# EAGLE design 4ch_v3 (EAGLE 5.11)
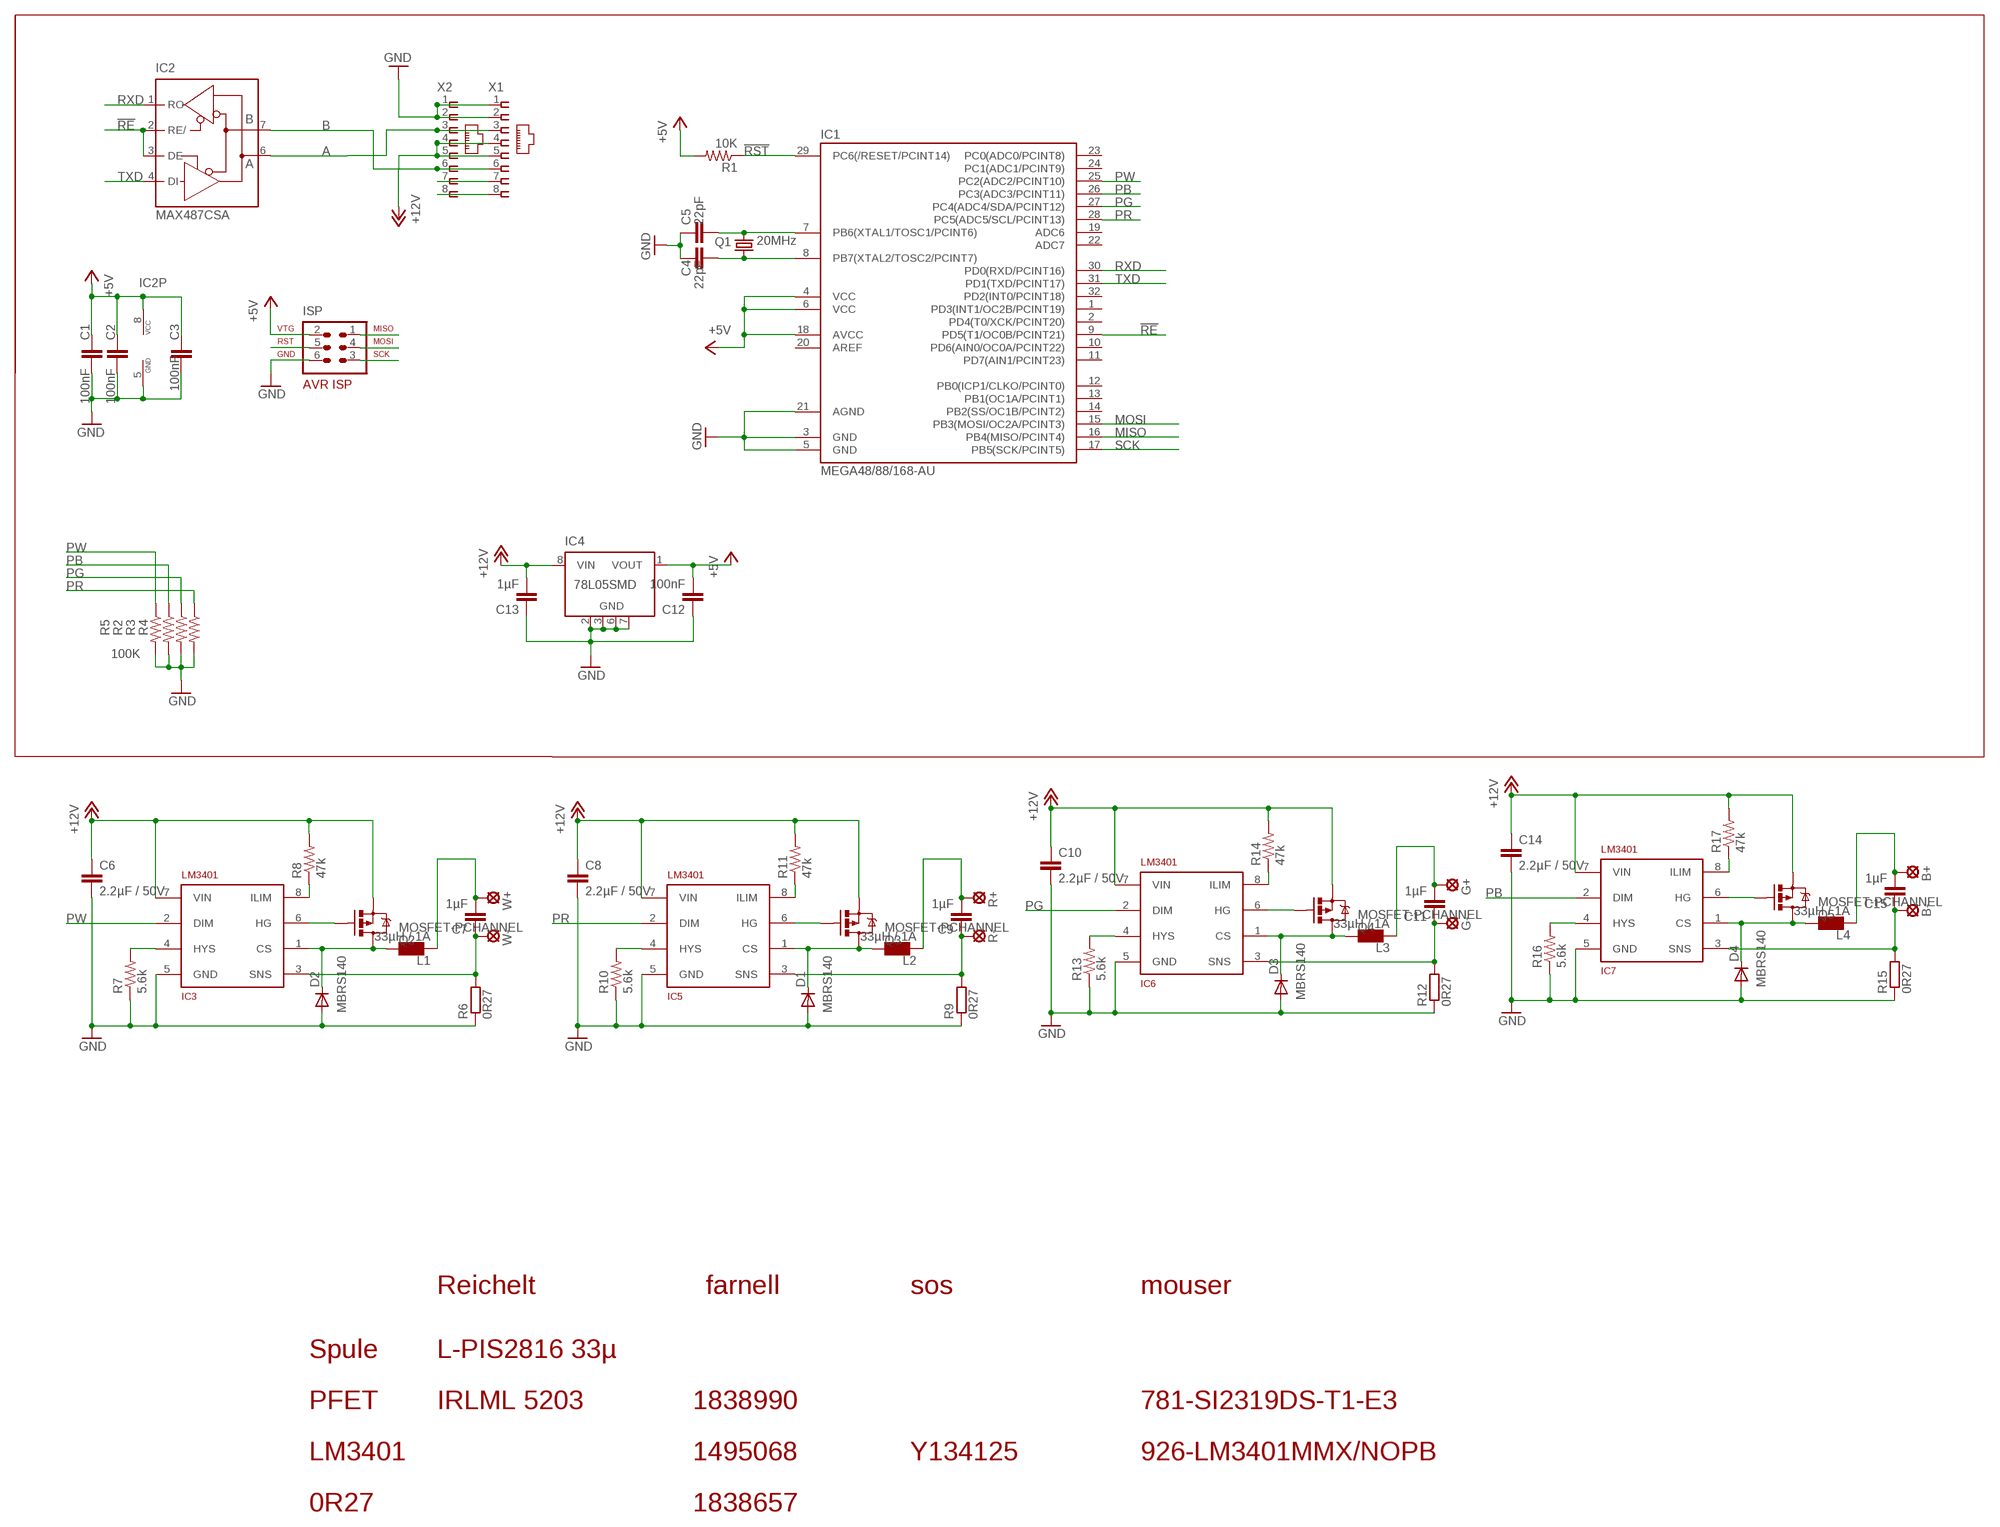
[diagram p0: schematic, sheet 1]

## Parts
B+  SE14  [SE14]
B-  SE14  [SE14]
C1  100nF  CAP0402-CAP  [0402-CAP]
C2  100nF  CAP0402-CAP  [0402-CAP]
C3  100nF  CAP0402-CAP  [0402-CAP]
C4  22pF  CAP0402-CAP  [0402-CAP]
C5  22pF  CAP0402-CAP  [0402-CAP]
C6  2.2µF / 50V  C-EUC1210  [C1210]
C7  1µF  CAP0805  [0805]
C8  2.2µF / 50V  C-EUC1210  [C1210]
C9  1µF  CAP0805  [0805]
C10  2.2µF / 50V  C-EUC1210  [C1210]
C11  1µF  CAP0805  [0805]
C12  100nF  CAP0402-CAP  [0402-CAP]
C13  1µF  CAP0805  [0805]
C14  2.2µF / 50V  C-EUC1210  [C1210]
C15  1µF  CAP0805  [0805]
D1  MBRS140  DIODE-SMB  [SMB]
D2  MBRS140  DIODE-SMB  [SMB]
D3  MBRS140  DIODE-SMB  [SMB]
D4  MBRS140  DIODE-SMB  [SMB]
G+  SE14  [SE14]
G-  SE14  [SE14]
IC1  MEGA48/88/168-AU  [TQFP32-08]
IC2  MAX487CSA  MAX481CSA  [SO08]
IC3  LM3401  [MSOP8]
IC4  78L05SMD  [SO08]
IC5  LM3401  [MSOP8]
IC6  LM3401  [MSOP8]
IC7  LM3401  [MSOP8]
ISP  AVR-ISP-6  [AVR-ISP-6]
L1  33µH / 1A  L_PIS2816  [PIS2816]
L2  33µH / 1A  L_PIS2816  [PIS2816]
L3  33µH / 1A  L_PIS2816  [PIS2816]
L4  33µH / 1A  L_PIS2816  [PIS2816]
Q1  20MHz  X22-OSCILLATOR  [X22]
Q2  MOSFET-PCHANNEL  [SOT23]
Q3  MOSFET-PCHANNEL  [SOT23]
Q4  MOSFET-PCHANNEL  [SOT23]
Q5  MOSFET-PCHANNEL  [SOT23]
R1  10K  RESISTOR0402-RES  [0402-RES]
R2  100K  RESISTOR0402-RES  [0402-RES]
R3  100K  RESISTOR0402-RES  [0402-RES]
R4  100K  RESISTOR0402-RES  [0402-RES]
R5  100K  RESISTOR0402-RES  [0402-RES]
R6  0R27  R-EU_R1206  [R1206]
R7  5.6k  RESISTOR0805-RES  [0805]
R8  47k  RESISTOR0805-RES  [0805]
R9  0R27  R-EU_R1206  [R1206]
R10  5.6k  RESISTOR0805-RES  [0805]
R11  47k  RESISTOR0805-RES  [0805]
R12  0R27  R-EU_R1206  [R1206]
R13  5.6k  RESISTOR0805-RES  [0805]
R14  47k  RESISTOR0805-RES  [0805]
R15  0R27  R-EU_R1206  [R1206]
R16  5.6k  RESISTOR0805-RES  [0805]
R17  47k  RESISTOR0805-RES  [0805]
R+  SE14  [SE14]
R-  SE14  [SE14]
W+  SE14  [SE14]
W-  SE14  [SE14]
X1  RJ45-8L-B  [RJ45-NO-SHIELD]
X2  RJ45-8L-B  [RJ45-NO-SHIELD]

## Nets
!RE: IC1.9(PD5(T1/OC0B/PCINT21)) IC2.2(RE/) IC2.3(DE)
!RST: IC1.29(PC6(/RESET/PCINT14)) ISP.5 R1.1
+5V: C1.1 C2.1 C3.1 C12.2 IC1.4(VCC) IC1.6(VCC) IC1.18(AVCC) IC2.8(VCC) IC4.1(VOUT) ISP.2 R1.2
+12V: C6.1 C8.1 C10.1 C13.2 C14.1 IC3.7(VIN) IC4.8(VIN) IC5.7(VIN) IC6.7(VIN) IC7.7(VIN) Q2.2(S) Q3.2(S) Q4.2(S) Q5.2(S) R8.2 R11.2 R14.2 R17.2 X1.4 X1.5 X2.4 X2.5
A: IC2.6(A) X1.3 X2.3
B: IC2.7(B) X1.6 X2.6
GND: C1.2 C2.2 C3.2 C4.1 C5.1 C6.2 C8.2 C10.2 C12.1 C13.1 C14.2 D1.A D2.A D3.A D4.A IC1.3(GND) IC1.5(GND) IC1.21(AGND) IC2.5(GND) IC3.5(GND) IC4.2(GND) IC4.3(GND) IC4.6(GND) IC4.7(GND) IC5.5(GND) IC6.5(GND) IC7.5(GND) ISP.6 R2.2 R3.2 R4.2 R5.2 R6.1 R7.1 R9.1 R10.1 R12.1 R13.1 R15.1 R16.1 X1.1 X1.2 X2.1 X2.2
MISO: IC1.16(PB4(MISO/PCINT4)) ISP.1
MOSI: IC1.15(PB3(MOSI/OC2A/PCINT3)) ISP.4
N$1: C7.1 IC3.3(SNS) R6.2 W-.MP
N$2: C7.2 L1.P$2 W+.MP
N$3: D2.C IC3.1(CS) L1.P$1 Q2.3(D)
N$4: C9.1 IC5.3(SNS) R9.2 R-.MP
N$5: IC3.4(HYS) R7.2
N$6: C9.2 L2.P$2 R+.MP
N$7: IC3.8(ILIM) R8.1
N$8: D1.C IC5.1(CS) L2.P$1 Q3.3(D)
N$9: IC5.4(HYS) R10.2
N$10: IC3.6(HG) Q2.1(G)
N$11: IC5.8(ILIM) R11.1
N$12: IC5.6(HG) Q3.1(G)
N$13: C11.1 G-.MP IC6.3(SNS) R12.2
N$14: C11.2 G+.MP L3.P$2
N$15: D3.C IC6.1(CS) L3.P$1 Q4.3(D)
N$16: IC6.4(HYS) R13.2
N$17: IC6.8(ILIM) R14.1
N$18: X1.7 X2.7
N$19: X1.8 X2.8
N$20: IC6.6(HG) Q4.1(G)
N$21: B-.MP C15.1 IC7.3(SNS) R15.2
N$22: B+.MP C15.2 L4.P$2
N$23: D4.C IC7.1(CS) L4.P$1 Q5.3(D)
N$24: IC7.4(HYS) R16.2
N$25: IC7.8(ILIM) R17.1
N$26: IC7.6(HG) Q5.1(G)
PB: IC1.26(PC3(ADC3/PCINT11)) IC7.2(DIM) R2.1
PG: IC1.27(PC4(ADC4/SDA/PCINT12)) IC6.2(DIM) R3.1
PR: IC1.28(PC5(ADC5/SCL/PCINT13)) IC5.2(DIM) R4.1
PW: IC1.25(PC2(ADC2/PCINT10)) IC3.2(DIM) R5.1
RXD: IC1.30(PD0(RXD/PCINT16)) IC2.1(RO)
SCK: IC1.17(PB5(SCK/PCINT5)) ISP.3
TXD: IC1.31(PD1(TXD/PCINT17)) IC2.4(DI)
XTAL1: C5.2 IC1.7(PB6(XTAL1/TOSC1/PCINT6)) Q1.3
XTAL2: C4.2 IC1.8(PB7(XTAL2/TOSC2/PCINT7)) Q1.1
Unconnected: IC1.1(PD3(INT1/OC2B/PCINT19)) IC1.2(PD4(T0/XCK/PCINT20)) IC1.10(PD6(AIN0/OC0A/PCINT22)) IC1.11(PD7(AIN1/PCINT23)) IC1.12(PB0(ICP1/CLKO/PCINT0)) IC1.13(PB1(OC1A/PCINT1)) IC1.14(PB2(SS/OC1B/PCINT2)) IC1.19(ADC6) IC1.20(AREF) IC1.22(ADC7) IC1.23(PC0(ADC0/PCINT8)) IC1.24(PC1(ADC1/PCINT9)) IC1.32(PD2(INT0/PCINT18)) IC4.4(NC) IC4.5(NC)

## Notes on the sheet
- Reichelt | farnell | sos | mouser
- Spule | L-PIS2816 33µ
- PFET | IRLML 5203 | 1838990 | 781-SI2319DS-T1-E3
- LM3401 | 1495068 | Y134125 | 926-LM3401MMX/NOPB
- 0R27 | 1838657

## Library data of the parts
B+ B- G+ G- R+ R- W+ W- = solpad:SE14: SOLDER PAD
C1-C5 C7 C9 C11-C13 C15 = SparkFun:CAP: Capacitor
C6 C8 C10 C14 = rcl:C-EU: CAPACITOR, European symbol
D1-D4 = diode:DIODE-: DIODE
IC1 = avr-7:MEGA48/88/168
IC2 = maxim:MAX481CSA: RS485 TRANSEIVER; MF: MAXIM; MPN: MAX481CSA; OC_FARNELL: unknown; OC_NEWARK: 90C3817
IC3 IC5-IC7 = seb:LM3401
IC4 = linear:78L*SMD: Positive VOLTAGE REGULATOR
ISP = atmel:AVR-ISP-6: AVR ISP-6 Serial Programming Header
L1-L4 = seb:L_PIS2816
Q1 = seb:X22-OSCILLATOR
Q2-Q5 = SparkFun:MOSFET-PCHANNEL
R1-R5 R7 R8 R10 R11 R13 R14 R16 R17 = SparkFun:RESISTOR: Resistor
R6 R9 R12 R15 = rcl:R-EU_: RESISTOR, European symbol
X1 X2 = con-tycoelectronics:RJ45: CORCOM Modular RJ Jacks No Shield Source: www.tycoelectronics.com .. ENG_DS_1654001_1099_RJ_L_0507.pdf; MF: TYCO ELECTRONICS; MPN: RJ45-8L-B; OC_FARNELL: 1279843; OC_NEWARK: 52K4445

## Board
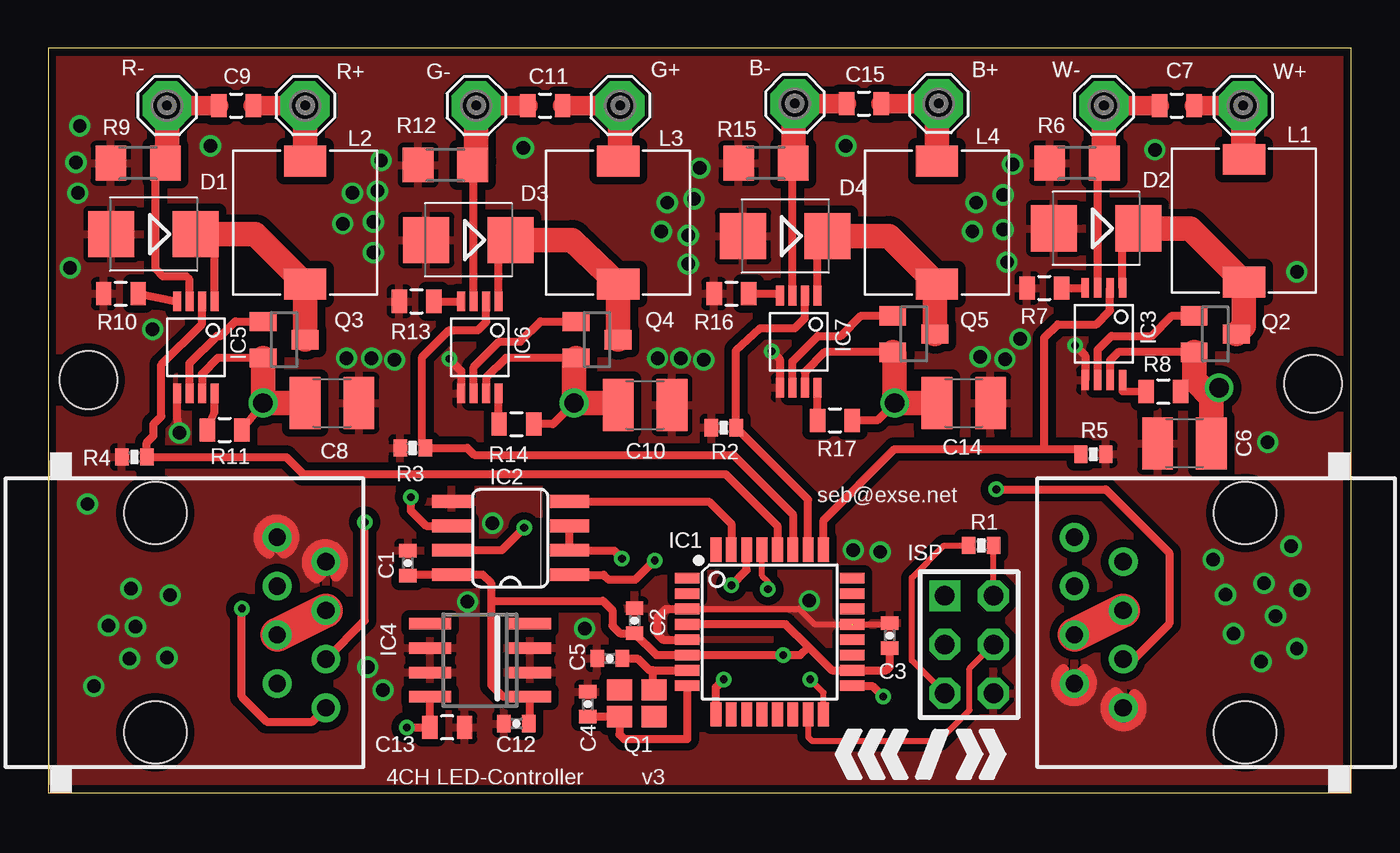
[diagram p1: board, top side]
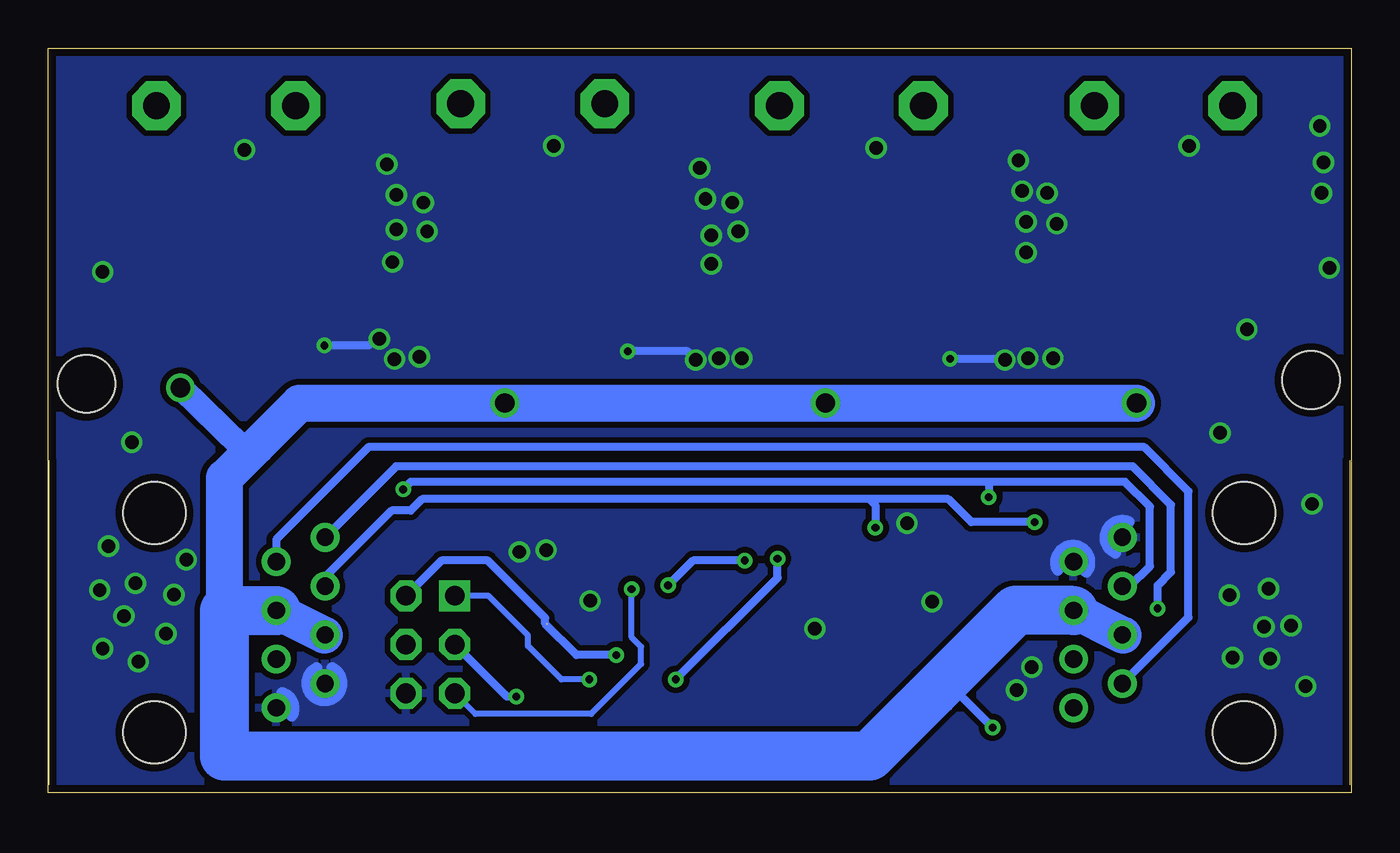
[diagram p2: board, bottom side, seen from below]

Size 67.9 x 38.8 mm. Coordinates in mm from the lower left corner, seen from the top.
Outline: 0,0 67.9,0 67.9,38.8 0,38.8 0,0
Copper layers (1*16): Top 0.035mm / dielectric 1.5mm / Bottom 0.035mm
Design rules "default *": minimum track width 0.2mm, minimum drill 0.5mm, track to track 0.2mm, track to pad 0.2mm, pad to pad 0.2mm, via to via 0.2mm, smd to smd 0mil, copper to edge 0.4mm, drill to drill 8mil, minimum pad ring 0.3mm, minimum via ring 8mil, stop-mask expansion 4mil, vias tented up to drill 40mil, thermal gap 10mil
Holes 3 mm at 2.1,21.5 65.9,21.3

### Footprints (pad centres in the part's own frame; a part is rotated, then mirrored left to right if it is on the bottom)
SE14 = drill 1.397 pad 2.54 octagon: MP 0,0
0402-CAP = smd 0.7 x 0.9: 1 -0.65,0; 2 0.65,0
C1210 = smd 1.6 x 2.7: 1 -1.4,0; 2 1.4,0
0805 = smd 0.8 x 1.2: 1 -0.9,0; 2 0.9,0
SMB = smd 2.4 x 2.4: A 2.2,0; C -2.2,0
TQFP32-08 = smd 1.27 x 0.559: 1 -4.293,2.8; 2 -4.293,2; 3 -4.293,1.2; 4 -4.293,0.4; 5 -4.293,-0.4; 6 -4.293,-1.2; 7 -4.293,-2; 8 -4.293,-2.8; 17 4.293,-2.8; 18 4.293,-2; 19 4.293,-1.2; 20 4.293,-0.4; 21 4.293,0.4; 22 4.293,1.2; 23 4.293,2; 24 4.293,2.8 | smd 0.559 x 1.27: 9 -2.8,-4.293; 10 -2,-4.293; 11 -1.2,-4.293; 12 -0.4,-4.293; 13 0.4,-4.293; 14 1.2,-4.293; 15 2,-4.293; 16 2.8,-4.293; 25 2.8,4.293; 26 2,4.293; 27 1.2,4.293; 28 0.4,4.293; 29 -0.4,4.293; 30 -1.2,4.293; 31 -2,4.293; 32 -2.8,4.293
SO08 = smd 0.66 x 2.032: 1 -1.905,-3.073; 2 -0.635,-3.073; 3 0.635,-3.073; 4 1.905,-3.073; 5 1.905,3.073; 6 0.635,3.073; 7 -0.635,3.073; 8 -1.905,3.073
MSOP8 = smd 0.41 x 1.02: 1 -0.975,-2.4; 2 -0.325,-2.4; 3 0.325,-2.4; 4 0.975,-2.4; 5 0.975,2.4; 6 0.325,2.4; 7 -0.325,2.4; 8 -0.975,2.4
SO08' = smd 0.6 x 2.2: 1 -1.905,-2.6; 2 -0.635,-2.6; 3 0.635,-2.6; 4 1.905,-2.6; 5 1.905,2.6; 6 0.635,2.6; 7 -0.635,2.6; 8 -1.905,2.6
AVR-ISP-6 = drill 1.016 square: 1 -2.54,-1.27 | drill 1.016 octagon: 2 -2.54,1.27; 3 0,-1.27; 4 0,1.27; 5 2.54,-1.27; 6 2.54,1.27
PIS2816 = smd 2.2 x 1.6: P$1 0,3.2; P$2 0,-3.2
X22 = smd 1.3 x 1.1: 1 0.9,0.7; 2 -0.9,0.7; 3 -0.9,-0.7; 4 0.9,-0.7
SOT23 = smd 1 x 1.4: 1 -0.95,-1.1; 2 0.95,-1.1; 3 0,1.1
0402-RES = smd 0.7 x 0.9: 1 -0.65,0; 2 0.65,0
R1206 = smd 1.6 x 1.803: 1 -1.422,0; 2 1.422,0
RJ45-NO-SHIELD = drill 0.9 pad 1.4 round: 1 -4.445,6.35; 2 -3.175,8.89; 3 -1.905,6.35; 4 -0.635,8.89; 5 0.635,6.35; 6 1.905,8.89; 7 3.175,6.35; 8 4.445,8.89 | hole 3.251: -5.715,0; 5.715,0

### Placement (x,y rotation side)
B+  46.4,35.9 0 top
B-  38.9,35.9 0 top
C1  18.75,11.97 90 top
C2  30.56,8.96 90 top
C3  43.85,8.19 90 top
C4  28.12,4.61 270 top
C5  29.26,6.99 0 top
C6  59.2,18.2 180 top
C7  58.8,35.8 0 top
C8  14.8,20.3 0 top
C9  9.8,35.8 0 top
C10  31.1,20.2 0 top
C11  25.9,35.8 0 top
C12  24.4,3.6 0 top
C13  20.8,3.4 180 top
C14  47.7,20.3 0 top
C15  42.5,35.9 0 top
D1  5.5,29.1 180 top
D2  54.6,29.4 180 top
D3  21.9,28.8 180 top
D4  38.4,29 180 top
G+  29.8,35.8 0 top
G-  22.3,35.8 0 top
IC1  37.59,8.37 0 top
IC2  24.08,13.26 90 top
IC3  55,23.9 180 top
IC4  78L05SMD  [SO08']  22.5,6.9 90 top
IC5  7.7,23.2 180 top
IC6  22.5,23.2 180 top
IC7  39.1,23.5 180 top
ISP  47.98,7.72 270 top
L1  62.3,29.8 180 top
L2  13.4,29.7 180 top
L3  29.7,29.7 180 top
L4  46.3,29.7 180 top
Q1  30.67,4.66 180 top
Q2  60.8,23.9 270 top
Q3  12.3,23.6 270 top
Q4  28.6,23.6 270 top
Q5  45.1,23.9 270 top
R1  48.61,12.88 0 top
R2  35.2,19.02 180 top
R3  19,17.96 180 top
R4  4.5,17.49 180 top
R5  54.45,17.63 0 top
R6  53.6,32.8 0 top
R7  51.9,26.3 0 top
R8  58.1,20.9 0 top
R9  4.7,32.8 0 top
R10  3.8,26 0 top
R11  9.2,18.9 0 top
R12  20.7,32.7 0 top
R13  19.2,25.6 0 top
R14  24.4,19.2 0 top
R15  37.4,32.8 0 top
R16  35.6,26 0 top
R17  41,19.4 0 top
R+  13.4,35.8 0 top
R-  6.2,35.8 0 top
W+  62.25,35.8 0 top
W-  55,35.8 0 top
X1  62.36,8.86 90 top
X2  5.59,8.86 270 top

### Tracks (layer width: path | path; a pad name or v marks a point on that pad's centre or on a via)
!RE  (via drill 0.4)
  Top 0.406: 34.8,4 IC1.9 34.8,5.5 v35.2,5.9 | IC2.3 IC2.2 27.19,12.6 29.5,12.6 v29.9,12.2
  Bottom 0.406: v29.9,12.2 29.9,11.2 v35.2,5.9
!RST  (via drill 0.4)
  Top 0.305: IC1.29 37.2,11.3 37.5,11 v37.5,10.6 | ISP.5 45,6.88 45,11.2 46.68,12.88 R1.1
  Bottom 0.305: v37.5,10.6 37.5,8.1 37,7.6 37,6.7 39.6,4.1 45.63,4.1 ISP.5
+5V  (via drill 0.4)
  Top 0.305: R1.2 49.25,12.87 ISP.2
  Top 0.406: 39.6,7.6 38.43,8.77 IC1.4 | 39.6,7.6 40.83,6.37 IC1.18 43.67,6.37 43.85,6.55 C3.1 | 39.6,7.6 39.17,7.17 v38.3,7.17 IC1.6 31.69,7.17 C2.1 29.79,8.31 29.4,8.7 29.4,9.5 28.9,10 23.1,10 | C12.2 25.1,3.55 IC4.1 23.7,5 23.1,5.6 23.1,10 | C1.1 18.79,11.36 IC2.8 22.64,11.36 23.1,10.9 23.1,10
  Bottom 0.406: v38.3,7.17 40.37,7.17 42,8.8 42,9.1 45,12.1 47.4,12.1 ISP.2
+12V  (via drill 0.4, 1)
  Top 0.406: IC5.7 8.03,21.82 8.85,22.65 Q3.2 | IC6.7 22.82,21.62 23.85,22.65 Q4.2 | IC7.7 39.42,21.93 40.45,22.95 Q5.2 | IC3.7 55.33,22.52 55.75,22.95 Q2.2 | R17.2 43.2,19.4 v44.1,20.3 | R14.2 26.3,19.2 v27.4,20.3 | v11.2,20.3 R11.2 | IC4.8 C13.2 v18.7,3.4
  Top 0.61: R8.2 59.7,21.6 59.7,21.8
  Top 1.27: C8.1 v11.2,20.3 Q3.2 | C10.1 29.6,20.3 v27.4,20.3 27.4,22.55 Q4.2 | C14.1 v44.1,20.3 44.1,22.85 Q5.2 | 60.6,20.6 C6.1 | 60.6,20.6 59.7,21.5 59.7,21.8 Q2.2 | 60.6,20.6 61,21 v61,21.1
  Top 1.778: X2.5 X2.4 | X1.5 X1.4
  Bottom 0.406: v18.7,3.4 20.55,5.25 21.75,5.25
  Bottom 1.27: v61,21.1 57.85,18.05 57.05,18.05
  Bottom 1.93: v11.2,20.3 v27.4,20.3 v44.1,20.3 54.8,20.3 57.05,18.05 58.7,16.4 58.7,9.49
  Bottom 2.54: X2.4 17.5,9.5 21.75,5.25 25.1,1.9 58.7,1.9 58.7,9.49 X1.5
A  (via drill 0.4)
  Top 0.406: X1.3 56.55,6.96 58.4,8.8 58.4,12.5 55.1,15.8 v49.4,15.8 | IC2.6 19.7,13.9 18.9,14.7 v18.9,15.4
  Bottom 0.406: v49.4,15.8 49,16.2 18.9,16.2 | X2.3 11.54,10.77 10.5,11.8 10.5,14.9 11.8,16.2 18.9,16.2 | 18.9,16.2 v18.9,15.4
B  (via drill 0.4)
  Top 0.406: v16.5,14.1 16.5,8.98 X2.6 | IC2.7 23.63,12.63 v24.8,13.8
  Bottom 0.406: 25.1,15.3 48.4,15.3 49,14.7 50,14.7 53.44,11.27 X1.6 | v24.8,13.8 24.8,15 25.1,15.3 | v16.5,14.1 19.8,14.1 21,15.3 25.1,15.3
GND  (via drill 0.4, 0.7)  (1 unrouted)
  Top 0.305: 41.93,8.77 43.89,8.77 | IC1.21 39.93,8.77 39.1,9.6 39.07,9.57 IC1.3
  Top 0.406: IC1.5 32.03,7.97 31.75,8.25 31.75,9.14 32.19,9.57 IC1.3 | IC5.5 6.72,19.57 v6.85,18.74 | IC3.5 54.02,22.77 v53.5,23.3 | IC7.5 38.12,22.57 v37.7,23 | IC6.5 21.52,21.98 v20.9,22.6
  Top 0.61: 52.9,6.4 arc284 54,6.4 53.47,5.87 X1.2 | 56.6,5.1 arc-293 55.6,5.2 56.01,4.79 X1.1 | 11.5,12.5 arc-307 12.3,12.5 11.94,12.86 X2.1 | 15,11.3 arc293 14,11.2 14.48,11.68 X2.2
  Bottom 0.406: v53.5,23.3 51.2,23.3 v50.64,23.64 | v37.7,23 34.61,23 v34.15,22.54 | v20.9,22.6 18.11,22.6 v18.05,22.54
  Bottom 0.61: 12.3,12.5 arc180 11.6,14.1 11.94,13.76 X2.1 | 15.3,11.6 arc242 13.8,11.5 14.34,12.04 X2.2 | 53.9,6.5 arc-307 53.1,6.5 53.1,6.05 X1.2 | 55.2,4 arc-100 55.7,5.2 55.7,4.72 X1.1
  other vias: 57.66,33.5 4.55,8.64 39.66,10 65.2,10.56 63.2,6.82 63.54,18.26 49.85,22.59 48.56,22.71 3.15,8.7 2.38,5.54 60.7,12.14 6.36,10.3 65.05,7.51 4.25,6.99 4.32,10.63 63.95,9.21 6.19,7.03 61.75,8.29 63.35,10.91 61.34,10.32 32.95,22.64 31.75,22.64 15.55,22.64 16.85,22.64 16.95,28.14 16.95,29.74 17.15,31.34 17.35,32.94 1.15,27.34 1.55,31.24 1.45,32.84 1.65,34.74 49.95,27.64 49.75,29.34 49.75,31.14 50.25,32.74 33.35,27.54 33.35,29.04 33.65,30.94 33.95,32.54 15.35,29.64 15.85,31.24 31.95,29.24 32.25,30.74 48.15,29.24 48.35,30.74 64.75,12.84 65.05,27.14 16.65,6.54 17.45,5.34 23.15,14.04 43.35,12.54 21.85,9.94 41.95,12.64 27.95,8.54 41.56,33.7 24.76,33.6 8.46,33.7 5.45,24.14 2.05,15.04
  pour Bottom (isolate 0.305, rank 2): 0.04,38.78 0.1,0 67.89,0 67.88,38.78
  pour Top (isolate 0.406, rank 2): 0.01,38.75 0,0 67.82,0 67.88,38.78
MISO  (via drill 0.4)
  Top 0.305: v39.7,5.9 40.4,5.21 IC1.16
  Bottom 0.305: v39.7,5.9 41.15,5.9 42.9,7.65 42.9,8.2 44.96,10.26 ISP.1
MOSI
  Top 0.305: IC1.15 39.59,2.9 39.8,2.7 46.4,2.7 48,4.3 48,6.47 ISP.4
N$1
  Top 0.406: IC3.3 54.67,32.35 R6.2
  Top 1.016: W-.MP C7.1
  Top 1.27: W-.MP 55,32.82 R6.2
N$2
  Top 1.016: W+.MP C7.2
  Top 1.27: W+.MP 62.25,33.05 L1.P$2
N$3
  Top 0.406: IC3.1 55.98,28.68 D2.C
  Top 1.27: D2.C 59.5,29.4 L1.P$1 62.3,24.3 Q2.3
N$4
  Top 0.406: 5.88,32.55 R9.2 5.6,32.28 5.6,27.3 6,26.9 7.2,26.9 7.38,26.73 IC5.3
  Top 1.016: R-.MP C9.1
  Top 1.27: R9.2 6.2,32.88 R-.MP
N$5
  Top 0.406: R7.2 IC3.4
N$6
  Top 1.016: R+.MP C9.2
  Top 1.27: L2.P$2 R+.MP
N$7
  Top 0.406: IC3.8 55.98,20.93 R8.1
N$8
  Top 0.406: IC5.1 8.68,28.68 D1.C
  Top 1.27: D1.C 10.8,29.1 L2.P$1 Q3.3
N$9
  Top 0.406: R10.2 IC5.4
N$10
  Top 0.406: IC3.6 54.67,23.07 55.4,23.8 57.5,23.8 58.55,24.85 Q2.1
N$11
  Top 0.406: IC5.8 8.68,19.82 R11.1
N$12
  Top 0.406: IC5.6 7.38,22.38 8.8,23.8 9,23.8 9.75,24.55 Q3.1
N$13
  Top 0.406: IC6.3 22.18,32.25 R12.2
  Top 1.016: G-.MP C11.1
  Top 1.27: R12.2 22.3,32.88 G-.MP
N$14
  Top 1.016: G+.MP C11.2
  Top 1.27: L3.P$2 29.8,32.9 G+.MP
N$15
  Top 0.406: IC6.1 23.48,28.27 D3.C
  Top 1.27: D3.C 27.3,28.8 L3.P$1 Q4.3
N$16
  Top 0.406: R13.2 IC6.4
N$17
  Top 0.406: IC6.8 23.48,19.23 R14.1
N$18
  Bottom 0.406: X1.7 56.01,13.19 51.2,18 10.8,18 8.5,15.7 8.5,9.12 X2.7
N$19  (via drill 0.4)
  Top 0.406: v10.1,9.6 10.1,5 11.4,3.7 13.76,3.7 X2.8
  Bottom 0.406: X1.8 49.77,17 11.4,17 9.4,15 9.4,11.5 10.1,10.8 v10.1,9.6
N$20
  Top 0.406: IC6.6 22.18,22.18 23.5,23.5 24.6,23.5 25.65,24.55 Q4.1
N$21
  Top 0.406: IC7.3 38.77,32.05 R15.2
  Top 1.016: B-.MP C15.1
  Top 1.27: B-.MP 38.82,35.82 R15.2
N$22
  Top 1.016: B+.MP C15.2
  Top 1.27: B+.MP 46.3,35.8 L4.P$2
N$23
  Top 0.406: IC7.1 40.08,28.38 D4.C
  Top 1.27: D4.C 43.8,29 L4.P$1 46.2,26.4 Q5.3
N$24
  Top 0.406: R16.2 37.92,26 IC7.4
N$25
  Top 0.406: IC7.8 40.08,19.43 R17.1
N$26
  Top 0.406: IC7.6 38.77,22.48 40.1,23.8 41.3,23.8 42.35,24.85 Q5.1
N$27
  Bottom 1.93: 11.9,8.2 14.5,9.5
N$28
  Bottom 1.93: 53.5,8.2 56.1,9.5
PB
  Top 0.406: IC1.26 39.59,15.27 R2.1 35.85,23.05 37.1,24.2 38.9,24.2 39.42,24.73 IC7.2
PG
  Top 0.406: IC1.27 38.8,14.51 35.7,17.6 22.2,17.6 21.84,17.96 R3.1 19.5,18.11 19.5,22.7 20.9,24.1 22.4,24.1 22.82,24.52 IC6.2
PR
  Top 0.406: IC5.2 8.03,24.43 5.9,22.3 5.9,19.6 5.5,19.2 5.5,18.6 5.15,18.25 R4.1 12.41,17.49 13.3,16.6 35.3,16.6 37.99,13.9 IC1.28
PW
  Top 0.406: IC3.2 55.33,25.12 54.6,24.4 52.6,24.4 51.9,23.7 51.9,17.9 | 51.9,17.9 44.1,17.9 40.4,14.2 IC1.25 | R5.1 53.54,17.9 51.9,17.9
RXD  (via drill 0.4)
  Top 0.406: v35.6,10.8 36.4,11.6 IC1.30 | IC2.1 28.94,11.36 29.2,11.1 30.6,11.1 v31.6,12.1
  Bottom 0.406: v31.6,12.1 34.3,12.1 v35.6,10.8
SCK  (via drill 0.4)
  Top 0.305: IC1.17
  Top 0.406: IC1.17 42.94,5.56 v43.5,5
  Bottom 0.406: v43.5,5 43.99,5 ISP.3
TXD
  Top 0.406: IC1.31 35.59,14.01 34.43,15.17 IC2.4
XTAL1
  Top 0.406: 31.5,6.37 31.33,6.37 30.71,6.99 C5.2 | 31.5,6.37 IC1.7 | Q1.3 31.5,5.23 31.5,6.37
XTAL2
  Top 0.406: Q1.1 29.84,3.69 | IC1.8 33.3,2.8 30,2.8 29.77,3.03 Q1.1 | Q1.1 C4.2

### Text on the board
tPlace: seb@exse.net | 4CH LED-Controller | v3
_tNames: R- | C9 | R+ | G- | C11 | G+ | B- | C15 | B+ | W- | C7 | W+ | L1 | R9 | L2 | R12 | L3 | R15 | L4 | R6 | D1 | D3 | D4 | D2 | IC7 | IC3 | R10 | IC5 | Q3 | R13 | IC6 | Q4 | R16 | Q5 | R7 | Q2 | R8 | R5 | R17 | C14 | R4 | R11 | C8 | R14 | C10 | R2 | C6 | R3 | IC2 | R1 | IC1 | ISP | C1 | C2 | IC4 | C3 | C5 | Q1 | C13 | C12 | C4
_tValues: SE14 | SE14 | SE14 | SE14 | SE14 | SE14 | SE14 | SE14 | 33µH / 1A | 33µH / 1A | 1µF | 33µH / 1A | 33µH / 1A | 1µF | 1µF | 1µF | MBRS140 | MBRS140 | MBRS140 | MBRS140 | 0R27 | 0R27 | 0R27 | 0R27 | LM3401 | LM3401 | 5.6k | LM3401 | MOSFET-PCHANNEL | LM3401 | MOSFET-PCHANNEL | 5.6k | MOSFET-PCHANNEL | 5.6k | MOSFET-PCHANNEL | 5.6k | 2.2µF / 50V | 47k | 47k | 47k | 47k | 2.2µF / 50V | 2.2µF / 50V | 2.2µF / 50V | RJ45-8L-B | 100K | 78L05SMD | MEGA48/88/168-AU | 1µF | RJ45-8L-B | 100nF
